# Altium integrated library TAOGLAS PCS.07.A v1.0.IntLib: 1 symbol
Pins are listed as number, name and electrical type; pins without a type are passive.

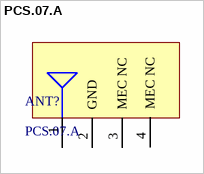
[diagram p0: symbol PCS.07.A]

## PCS.07.A
designator ANT?
GSM/CDMA/DCS/PCS/WCDMA/UMTS/HSDPA /GPRS/EDGE  824-960MHz, 1710-2170MHz; MFG: Taoglas; Temp_High: 85; Temp_Low: 40; ComponentLibStatus: Created
footprint Taoglas_PCS.07.B (GSM/CDMA/DCS/PCS/WCDMA/UMTS/HSDPA /GPRS/EDGE  824-960MHz, 1710-2170MHz)
pins: 1 RF OUT, 2 GND, 3 MEC NC, 4 MEC NC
